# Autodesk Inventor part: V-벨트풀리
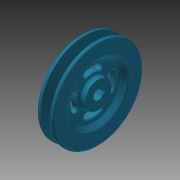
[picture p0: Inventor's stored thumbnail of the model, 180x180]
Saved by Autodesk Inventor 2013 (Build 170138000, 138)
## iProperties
Created: 2015-12
Part Number: V-벨트풀리
Document SubType Name: Modeling
Designer: mdu
Density: 8.08 g/cm^3
Material: 스테인리스강
Mass: 919.289 g
Surface Area: 326.109 cm^2
Volume: 113.773 cm^3
Author: mdu
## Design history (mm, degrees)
sketch "스케치1"
  geometry: L1 (-10, 0)-(10, 0); L2 (-10, 0)-(-10, 16); L3 (-10, 16)-(-4, 16); L4 (-4, 16)-(-4, 31); L5 (-4, 31)-(-10, 37); L6 (-10, 37)-(-10, 54.5); L7 (-10, 54.5)-(-5.976, 54.5); L8 (-5.976, 54.5)-(-2.154, 42); L9 (-2.154, 42)-(2.154, 42); L10 (2.154, 42)-(5.976, 54.5); L11 (5.976, 54.5)-(10, 54.5); L12 (10, 54.5)-(10, 37); L13 (10, 37)-(4, 31); L14 (4, 31)-(4, 16); L15 (4, 16)-(10, 16); L16 (10, 16)-(10, 0); L17 (-4.6, 50)-(4.6, 50); 2 further points
  constraints: 34 end point, 7 parallel, 6 equal length, 5 collinear, 3 perpendicular, 2 point on line, 1 coincident, 1 horizontal, 1 midpoint
  dimensions: "d0" = 20 distance of L1.start L1.end; "d1" = 9.2 distance of L17.start L17.end; "d2" = 34 deg angle of L10 L8; "d3" = 4.5 distance between parallel lines of L7 L17; "d4" = 8 distance between parallel lines of L9 L17; "d6" = 100 diameter of L17 L1; "d7" = 32 diameter of L3 L1; "d8" = 74 diameter of L5.end L1; "d9" = 6 distance of L2.end L3.end; "d10" = 135 deg angle of L4 L5
revolve "회전1" sketch "스케치1" stored, may be unused: angle "d11" = 90 deg
fillet "모깎기1" dims "d12" = 2, "d13" = 0.5, "d14" = 1, "d15" = 3
sketch "스케치2"
  geometry: L1 (-2, 5.657)-(-2, 7.8); L2 (-2, 7.8)-(2, 7.8); L3 (2, 7.8)-(2, 5.657); A1 r 6 centre (0, 0) between (-2, 5.657) and (2, 5.657); 1 further point
  constraints: 6 end point, 2 parallel, 2 point on circle, 1 centre point, 1 coincident, 1 perpendicular, 1 vertical
  dimensions: "d16" = 12 diameter of A1; "d17" = 4 distance of L1.end L2.end; "d18" = 13.8 dimension on A1 L2 (computed from d16)
extrude "돌출1" cut sketch "스케치2" stored distance "d19" = 10; taper "d20" = 0 deg
sketch "스케치3"
  geometry: L1 (0, 0)-(0, 24.5); L2 (0, 0)-(-8.379, 23.022); C1 r 29.757 at (0, 0) reference; C2 r 19 at (0, 0) reference; A1 r 24.5 centre (0, 0) between (0, 24.5) and (-8.379, 23.022); A2 r 3.3 centre (-8.379, 23.022) between (-9.508, 26.123) and (-7.251, 19.921); A3 r 3.3 centre (8.379, 23.022) between (7.251, 19.921) and (9.508, 26.123); A4 r 27.8 centre (0, 0) between (9.508, 26.123) and (-9.508, 26.123); A5 r 21.2 centre (0, 0) between (7.251, 19.921) and (-7.251, 19.921); 1 further point
  constraints: 10 point on circle, 5 centre point, 4 coincident, 4 end point, 1 point on line, 1 symmetric about line, 1 tangent, 1 vertical, 1 other
  dimensions: "d24" = 49 diameter of A1; "d27" = 20 deg angle of L1 L2; "d29" = 6.6 diameter of A2
extrude "돌출2" cut sketch "스케치3" stored distance "d30" = 10; taper "d31" = 0 deg
fillet "모깎기2" dims "d32" = 1
node "솔리드1"
pattern_circular "원형 패턴1" dims angle "d34" = 360 deg
